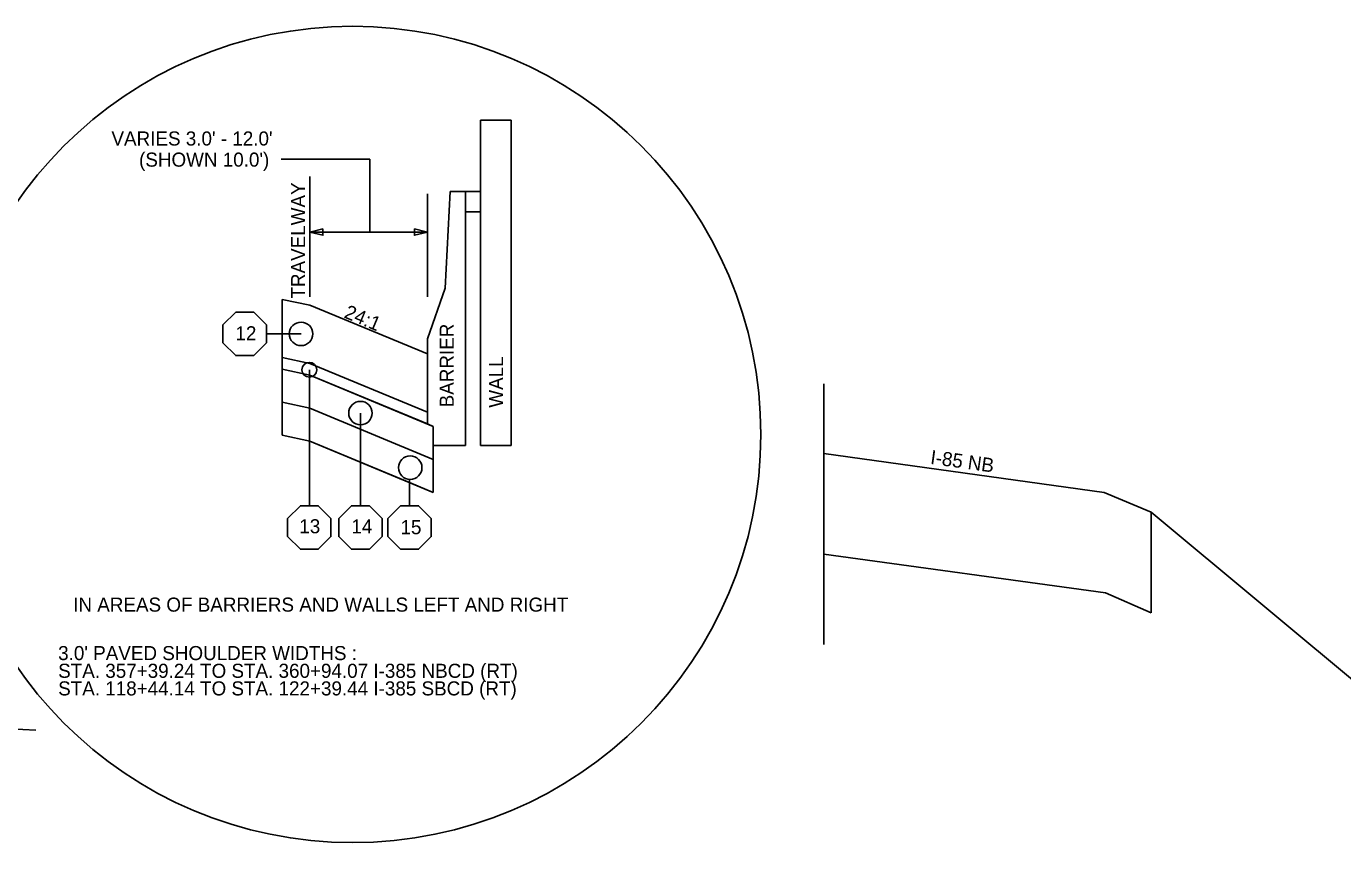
# Model space of a CAD drawing. Extents: x 5017 to 5774, y 4942 to 5266.
# Drawn here: x 5129.3 to 5241.5, y 5056.2 to 5125.8 of the extents above; entities that cross this region are included whole.
import ezdxf

# ---------------------------------------------------------------- set-up
doc = ezdxf.new("R2010")
doc.units = 0
for name, color, linetype in [('RD_QTY_Miscl_1', 7, 'Continuous'), ('RD_QTY_Miscl_2', 7, 'Continuous'), ('RD_QTY_Miscl_3', 7, 'Continuous'), ('RD_QTY_Stab_Agg_3', 7, 'Continuous'), ('RD_SHT_Typical', 7, 'Continuous'), ('RD_TX_TypSect', 7, 'Continuous'), ('RD_XS_CurbBase', 7, 'Continuous'), ('RD_XS_ExGround', 7, 'Continuous'), ('RD_XS_ExPaveRet', 7, 'Continuous'), ('RD_XS_MedBase', 7, 'Continuous'), ('typical_on', 7, 'Continuous')]:
    doc.layers.add(name, color=color, linetype=linetype)

msp = doc.modelspace()

# ---------------------------------------------------------------- linework, layer by layer
at = {"layer": 'RD_QTY_Miscl_1'}
for p, q in [((5151.12, 5097.55), (5151.12, 5096.55)), ((5153.48, 5097.06), (5151.12, 5097.55)), ((5151.12, 5096.55), (5153.48, 5096.06)), ((5163.48, 5092.89), (5153.48, 5097.06)), ((5153.48, 5096.06), (5163.48, 5091.9)), ((5163.48, 5091.9), (5163.48, 5092.89))]:
    msp.add_line(p, q, dxfattribs=at)
at = {"layer": 'RD_QTY_Miscl_2'}
for p, q in [((5151.12, 5096.55), (5151.12, 5093.74)), ((5153.48, 5096.06), (5151.12, 5096.55)), ((5151.12, 5093.74), (5153.48, 5093.25)), ((5153.48, 5093.25), (5163.98, 5088.88)), ((5163.98, 5088.88), (5163.98, 5091.69))]:
    msp.add_line(p, q, dxfattribs=at)
msp.add_lwpolyline([(5163.98, 5091.69), (5163.48, 5091.9), (5153.48, 5096.06)], dxfattribs=at)
at = {"layer": 'RD_QTY_Miscl_3'}
for p, q in [((5153.48, 5093.25), (5151.12, 5093.74)), ((5151.12, 5093.74), (5151.12, 5090.93)), ((5163.98, 5088.88), (5153.48, 5093.25)), ((5151.12, 5090.93), (5153.48, 5090.44)), ((5163.98, 5086.06), (5163.98, 5088.88))]:
    msp.add_line(p, q, dxfattribs=at)
msp.add_lwpolyline([(5153.48, 5090.44), (5161.97, 5086.9), (5163.98, 5086.06)], dxfattribs=at)
msp.add_circle((5162.02, 5088.17), 1, dxfattribs=at)
at = {"layer": 'RD_QTY_Stab_Agg_3'}
for p, q in [((5151.12, 5102.51), (5151.12, 5097.55)), ((5153.48, 5102.02), (5151.12, 5102.51)), ((5163.48, 5097.86), (5153.48, 5102.02)), ((5163.48, 5092.89), (5163.48, 5097.86)), ((5151.12, 5097.55), (5153.48, 5097.06)), ((5153.48, 5097.06), (5163.48, 5092.89))]:
    msp.add_line(p, q, dxfattribs=at)
at = {"layer": 'RD_SHT_Typical'}
for p, q in [((5151.12, 5090.93), (5151.12, 5102.51)), ((5153.48, 5102.02), (5163.48, 5097.86)), ((5163.48, 5097.84), (5163.48, 5091.9)), ((5151.12, 5096.55), (5153.48, 5096.06)), ((5163.48, 5092.89), (5153.48, 5097.06)), ((5163.98, 5091.69), (5153.48, 5096.06)), ((5197.25, 5073.09), (5197.25, 5095.3)), ((5151.12, 5093.74), (5153.48, 5093.25)), ((5163.98, 5088.88), (5153.48, 5093.25)), ((5151.12, 5090.93), (5153.48, 5090.44)), ((5163.98, 5091.69), (5163.98, 5086.06)), ((5163.98, 5086.06), (5153.48, 5090.44)), ((5225.14, 5084.38), (5244.66, 5068.11))]:
    msp.add_line(p, q, dxfattribs=at)
for points in [[(5151.12, 5102.51), (5153.48, 5102.02)], [(5151.12, 5097.55), (5153.48, 5097.06)]]:
    msp.add_lwpolyline(points, dxfattribs=at)
at = {"layer": 'RD_TX_TypSect'}
for p, q in [((5151.02, 5114.45), (5158.59, 5114.45)), ((5158.59, 5108.22), (5158.59, 5114.45)), ((5153.48, 5112.98), (5153.48, 5102.74)), ((5163.48, 5111.5), (5163.48, 5102.74)), ((5153.48, 5108.25), (5163.48, 5108.25)), ((5149.77, 5099.57), (5152.72, 5099.57)), ((5153.43, 5084.92), (5153.43, 5096.51)), ((5157.78, 5084.92), (5157.78, 5092.82)), ((5161.97, 5087.17), (5161.97, 5084.92))]:
    msp.add_line(p, q, dxfattribs=at)
for points in [[(5154.59, 5108.52), (5154.59, 5107.97), (5153.48, 5108.25)], [(5162.38, 5108.52), (5162.38, 5107.97), (5163.48, 5108.25)]]:
    msp.add_lwpolyline(points, close=True, dxfattribs=at)
for centre, radius in [((5157.11, 5091), 34.78), ((5152.72, 5099.57), 1), ((5153.43, 5096.51), 0.63), ((5157.78, 5092.82), 1), ((5162.02, 5088.17), 1)]:
    msp.add_circle(centre, radius, dxfattribs=at)
at = {"layer": 'RD_XS_CurbBase'}
for p, q in [((5166.72, 5111.69), (5166.72, 5109.96)), ((5168.02, 5111.69), (5168.02, 5109.96)), ((5163.48, 5097.86), (5163.48, 5091.9))]:
    msp.add_line(p, q, dxfattribs=at)
at = {"layer": 'RD_XS_ExGround'}
msp.add_line((5117.22, 5066.39), (5130.12, 5065.81), dxfattribs=at)
at = {"layer": 'RD_XS_ExPaveRet'}
for p, q in [((5197.25, 5089.37), (5221.14, 5086.04)), ((5221.14, 5086.04), (5197.25, 5089.37)), ((5197.25, 5089.37), (5197.25, 5080.79)), ((5221.14, 5086.04), (5225.14, 5084.38)), ((5225.14, 5084.38), (5221.14, 5086.04)), ((5225.14, 5084.38), (5225.14, 5075.79)), ((5225.14, 5075.79), (5225.14, 5084.38)), ((5221.25, 5077.49), (5197.25, 5080.79)), ((5197.25, 5080.79), (5221.25, 5077.49)), ((5221.25, 5077.49), (5225.14, 5075.79)), ((5221.25, 5077.49), (5225.14, 5075.79))]:
    msp.add_line(p, q, dxfattribs=at)
at = {"layer": 'RD_XS_MedBase'}
for p, q in [((5168.02, 5111.69), (5168.02, 5117.77)), ((5168.02, 5117.77), (5170.61, 5117.77)), ((5170.61, 5090.07), (5170.61, 5117.77)), ((5164.99, 5103.48), (5165.43, 5111.69)), ((5165.43, 5111.69), (5166.72, 5111.69)), ((5166.72, 5111.69), (5168.02, 5111.69)), ((5166.72, 5090.07), (5166.72, 5109.96)), ((5166.72, 5109.96), (5168.02, 5109.96)), ((5168.02, 5109.96), (5168.02, 5090.07)), ((5163.48, 5099.15), (5164.99, 5103.48)), ((5163.48, 5097.86), (5163.48, 5099.15)), ((5163.98, 5090.07), (5166.72, 5090.07)), ((5168.02, 5090.07), (5170.61, 5090.07))]:
    msp.add_line(p, q, dxfattribs=at)
at = {"layer": 'typical_on'}
for points in [[(5149.77, 5100.33), (5149.77, 5098.8), (5148.69, 5097.72), (5147.16, 5097.72), (5146.07, 5098.8), (5146.07, 5100.33), (5147.16, 5101.41), (5148.69, 5101.41)], [(5155.27, 5083.83), (5155.27, 5082.3), (5154.19, 5081.22), (5152.66, 5081.22), (5151.58, 5082.3), (5151.58, 5083.83), (5152.66, 5084.92), (5154.19, 5084.92)], [(5159.63, 5083.83), (5159.63, 5082.3), (5158.54, 5081.22), (5157.01, 5081.22), (5155.93, 5082.3), (5155.93, 5083.83), (5157.01, 5084.92), (5158.54, 5084.92)], [(5163.81, 5083.83), (5163.81, 5082.3), (5162.73, 5081.22), (5161.2, 5081.22), (5160.12, 5082.3), (5160.12, 5083.83), (5161.2, 5084.92), (5162.73, 5084.92)]]:
    msp.add_lwpolyline(points, close=True, dxfattribs=at)

# ---------------------------------------------------------------- texts
at = {"layer": 'RD_TX_TypSect'}
for s, p in [("VARIES 3.0' - 12.0'", (5136.57, 5115.62)), ("(SHOWN 10.0')", (5138.92, 5113.82)), ('12', (5147.13, 5099.02)), ('13', (5152.57, 5082.58)), ('14', (5157.01, 5082.57)), ('15', (5161.19, 5082.5)), ('IN AREAS OF BARRIERS AND WALLS LEFT AND RIGHT', (5133.31, 5075.9)), ("3.0' PAVED SHOULDER WIDTHS :", (5132.03, 5071.77)), ('STA. 357+39.24 TO STA. 360+94.07 I-385 NBCD (RT)', (5132.03, 5070.26)), ('STA. 118+44.14 TO STA. 122+39.44 I-385 SBCD (RT)', (5132.03, 5068.76))]:
    msp.add_text(s, height=1.2, dxfattribs=at).set_placement(p)
for s, rotation, p in [('TRAVELWAY', 90, (5153.07, 5102.58)), ('24:1', 337.3801, (5156.31, 5100.98)), ('BARRIER', 90, (5165.73, 5093.31)), ('WALL', 90, (5169.93, 5093.28)), ('I-85 NB', 352.0761, (5206.28, 5088.5))]:
    msp.add_text(s, height=1.2, rotation=rotation, dxfattribs=at).set_placement(p)

doc.saveas('drawing.dxf')
